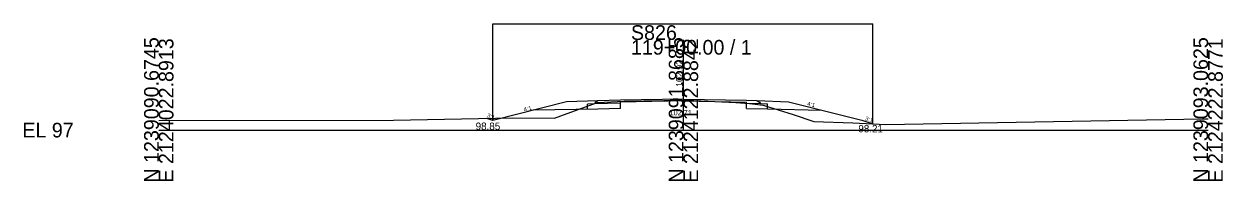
# Model space of a CAD drawing. Extents: x 2119282 to 2119710, y 1215030 to 1220057.
# Drawn here: x 2119381.9 to 2119610.4, y 1217530.1 to 1217560 of the extents above; entities that cross this region are included whole.
import ezdxf

# ---------------------------------------------------------------- set-up
doc = ezdxf.new("R2010")
doc.units = 0
for name, color, linetype in [('XS_CELL', 7, 'Continuous'), ('XS_M_DITCH', 7, 'Continuous'), ('XS_P_FINISHED_GRADE', 7, 'Continuous'), ('XS_P_FINISHED_GRADE_ELEV_TX', 7, 'Continuous'), ('XS_P_SUBGRADE_GRANULAR', 7, 'Continuous'), ('XS_P_SUBGRADE_PAVEMENT', 7, 'Continuous'), ('XS_P_TX_DCH', 7, 'Continuous'), ('XS_P_TX_FS_BS', 7, 'Continuous'), ('XS_X_GROUND', 7, 'Continuous'), ('XS_X_GROUND_TX', 7, 'Continuous')]:
    doc.layers.add(name, color=color, linetype=linetype)

msp = doc.modelspace()

# ---------------------------------------------------------------- linework, layer by layer
at = {"layer": 'XS_CELL'}
for p, q in [((2119507.6, 1217539.8), (2119507.6, 1217556.97)), ((2119407.6, 1217539.8), (2119507.6, 1217539.8)), ((2119507.6, 1217539.8), (2119607.6, 1217539.8))]:
    msp.add_line(p, q, dxfattribs=at)
at = {"layer": 'XS_M_DITCH'}
for p, q in [((2119471.29, 1217541.66), (2119471.29, 1217560.01)), ((2119471.29, 1217560.01), (2119543.67, 1217560.01)), ((2119543.67, 1217541.01), (2119543.67, 1217560.01))]:
    msp.add_line(p, q, dxfattribs=at)
at = {"layer": 'XS_P_FINISHED_GRADE'}
for p, q in [((2119485.29, 1217545.16), (2119471.29, 1217541.66)), ((2119491.29, 1217545.4), (2119485.29, 1217545.16)), ((2119495.6, 1217545.48), (2119491.29, 1217545.4)), ((2119507.6, 1217545.72), (2119495.6, 1217545.48)), ((2119507.6, 1217545.72), (2119519.6, 1217545.48)), ((2119519.6, 1217545.48), (2119521.6, 1217545.44)), ((2119521.6, 1217545.44), (2119527.6, 1217545.2)), ((2119527.6, 1217545.2), (2119541.6, 1217541.7)), ((2119471.29, 1217541.66), (2119470.13, 1217542.04)), ((2119541.6, 1217541.7), (2119543.67, 1217541.01))]:
    msp.add_line(p, q, dxfattribs=at)
at = {"layer": 'XS_P_SUBGRADE_GRANULAR'}
for p, q in [((2119490.64, 1217544.8), (2119489.29, 1217544.75)), ((2119489.29, 1217543.77), (2119489.29, 1217544.75)), ((2119495.6, 1217543.9), (2119495.61, 1217544.9)), ((2119519.6, 1217543.9), (2119519.59, 1217544.9)), ((2119522.26, 1217544.85), (2119523.6, 1217544.79)), ((2119523.6, 1217543.82), (2119523.6, 1217544.79)), ((2119491.29, 1217543.81), (2119478.93, 1217543.57)), ((2119495.6, 1217543.9), (2119491.29, 1217543.81)), ((2119519.6, 1217543.9), (2119523.6, 1217543.82)), ((2119523.6, 1217543.82), (2119533.97, 1217543.61))]:
    msp.add_line(p, q, dxfattribs=at)
at = {"layer": 'XS_P_SUBGRADE_PAVEMENT'}
for p, q in [((2119490.79, 1217545.05), (2119490.64, 1217544.8)), ((2119495.61, 1217544.9), (2119490.64, 1217544.8)), ((2119491.29, 1217545.4), (2119490.79, 1217545.05)), ((2119507.6, 1217545.39), (2119495.61, 1217545.15)), ((2119495.61, 1217544.9), (2119495.61, 1217545.15)), ((2119507.6, 1217545.39), (2119519.6, 1217545.15)), ((2119519.59, 1217544.9), (2119519.6, 1217545.15)), ((2119519.59, 1217544.9), (2119522.26, 1217544.85)), ((2119521.6, 1217545.44), (2119522.11, 1217545.1)), ((2119522.11, 1217545.1), (2119522.26, 1217544.85))]:
    msp.add_line(p, q, dxfattribs=at)
at = {"layer": 'XS_X_GROUND'}
for p, q in [((2119485.42, 1217542.97), (2119491.23, 1217545.05)), ((2119491.23, 1217545.05), (2119496.32, 1217545.28)), ((2119496.32, 1217545.28), (2119507.6, 1217545.51)), ((2119507.6, 1217545.51), (2119508.25, 1217545.52)), ((2119508.25, 1217545.52), (2119517.59, 1217545.03)), ((2119517.59, 1217545.03), (2119520.17, 1217544.89)), ((2119520.17, 1217544.89), (2119520.79, 1217544.83)), ((2119520.79, 1217544.83), (2119522.79, 1217544.57)), ((2119522.79, 1217544.57), (2119528.51, 1217542.75)), ((2119407.6, 1217541.65), (2119452.32, 1217541.72)), ((2119452.32, 1217541.72), (2119475.03, 1217542.13)), ((2119475.03, 1217542.13), (2119483.05, 1217542.1)), ((2119483.05, 1217542.1), (2119485.42, 1217542.97)), ((2119528.51, 1217542.75), (2119532.45, 1217541.46)), ((2119546.17, 1217540.9), (2119606.5, 1217541.93)), ((2119606.5, 1217541.93), (2119607.6, 1217541.95)), ((2119532.45, 1217541.46), (2119539.86, 1217541.18)), ((2119539.86, 1217541.18), (2119546.17, 1217540.9))]:
    msp.add_line(p, q, dxfattribs=at)

# ---------------------------------------------------------------- texts
at = {"layer": 'XS_CELL'}
for s, p in [('S826', (2119497.6, 1217556.97)), ('119+00.00 / 1', (2119497.6, 1217554.17)), ('EL 97', (2119381.6, 1217538.4))]:
    msp.add_text(s, height=2.8, dxfattribs=at).set_placement(p)
for s, p in [('N 1239090.6745', (2119407.6, 1217529.8)), ('E 2124022.8913', (2119410.4, 1217529.8)), ('N 1239091.8685', (2119507.6, 1217529.8)), ('E 2124122.8842', (2119510.4, 1217529.8)), ('N 1239093.0625', (2119607.6, 1217529.8)), ('E 2124222.8771', (2119610.4, 1217529.8))]:
    msp.add_text(s, height=2.8, rotation=90, dxfattribs=at).set_placement(p)
at = {"layer": 'XS_P_FINISHED_GRADE_ELEV_TX'}
msp.add_text('102.92', height=1.25, rotation=90, dxfattribs=at).set_placement((2119507.45, 1217548.04))
at = {"layer": 'XS_P_TX_DCH'}
for s, p in [('98.85', (2119468, 1217539.84)), ('98.21', (2119540.94, 1217539.38))]:
    msp.add_text(s, height=1.4, dxfattribs=at).set_placement(p)
at = {"layer": 'XS_P_TX_FS_BS'}
for s, rotation, p in [('4:1', 14.0362, (2119477.24, 1217543.31)), ('4:1', 345.9638, (2119531.11, 1217544.5)), ('3:1', 341.5651, (2119470.07, 1217542.27)), ('3:1', 341.5651, (2119542.15, 1217541.69))]:
    msp.add_text(s, height=0.8, rotation=rotation, dxfattribs=at).set_placement(p)
at = {"layer": 'XS_X_GROUND_TX'}
msp.add_text('102.71', height=1, dxfattribs=at).set_placement((2119504.96, 1217542.61))

doc.saveas('drawing.dxf')
